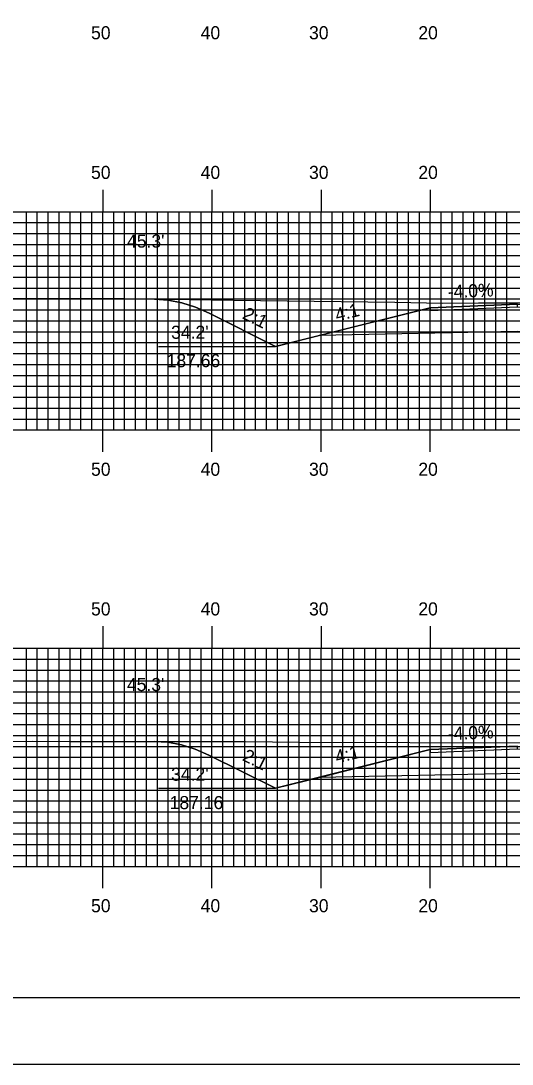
# Model space of a CAD drawing. Extents: x 1798781 to 1799124, y 442591 to 442811.
# Drawn here: x 1798889.5 to 1798934.5, y 442590.5 to 442686.2 of the extents above; entities that cross this region are included whole.
import ezdxf

# ---------------------------------------------------------------- set-up
doc = ezdxf.new("R2010")
doc.units = 0
for name, color, linetype in [('ANNOTATION', 7, 'Continuous'), ('BORDER', 7, 'Continuous'), ('D_Roadway_Centerline', 7, 'Continuous'), ('D_Roadway_Edge_Shoulder', 7, 'Continuous'), ('D_Roadway_SlopeLines', 7, 'Continuous'), ('D_Roadway_SubGrade', 7, 'Continuous'), ('D_Text_Standard', 7, 'Continuous'), ('H_V ANNOTATION', 7, 'Continuous'), ('MAJOR', 7, 'Continuous'), ('MINOR', 7, 'Continuous'), ('PDRAIN', 7, 'Continuous'), ('PLOT BOUNDARY', 7, 'Continuous'), ('S_Roadway_Centerline', 7, 'Continuous')]:
    doc.layers.add(name, color=color, linetype=linetype)

msp = doc.modelspace()

# ---------------------------------------------------------------- linework, layer by layer
at = {"layer": 'BORDER'}
msp.add_lwpolyline([(1798797.384, 442596.665), (1799117.384, 442596.665), (1799117.384, 442806.665), (1798797.384, 442806.665)], close=True, dxfattribs=at)
at = {"layer": 'D_Roadway_Centerline'}
for points in [[(1798901.718, 442660.662), (1798902.968, 442660.566), (1798904.218, 442660.319), (1798905.468, 442659.921), (1798906.718, 442659.371), (1798912.81, 442656.325), (1798916.81, 442657.325), (1798926.984, 442659.869), (1798934.984, 442660.189), (1798946.984, 442659.949), (1798958.984, 442659.709), (1798966.984, 442659.389), (1798977.158, 442656.845), (1798981.158, 442655.845), (1798987.244, 442658.888), (1798988.494, 442659.435), (1798989.744, 442659.826), (1798990.994, 442660.06), (1798992.244, 442660.138)], [(1798901.708, 442620.125), (1798902.958, 442620.047), (1798904.208, 442619.813), (1798905.458, 442619.423), (1798906.708, 442618.876), (1798912.81, 442615.825), (1798916.81, 442616.825), (1798926.984, 442619.369), (1798934.984, 442619.689), (1798946.984, 442619.449), (1798958.984, 442619.209), (1798966.984, 442618.889), (1798977.158, 442616.345), (1798981.158, 442615.345), (1798987.068, 442618.3), (1798988.318, 442618.845), (1798989.568, 442619.228), (1798990.818, 442619.451), (1798992.068, 442619.513)]]:
    msp.add_lwpolyline(points, dxfattribs=at)
at = {"layer": 'D_Roadway_Edge_Shoulder'}
for points in [[(1798934.984, 442660.189), (1798926.984, 442659.869), (1798926.984, 442659.619), (1798934.984, 442659.939)], [(1798934.984, 442619.689), (1798926.984, 442619.369), (1798926.984, 442619.119), (1798934.984, 442619.439)]]:
    msp.add_lwpolyline(points, close=True, dxfattribs=at)
at = {"layer": 'D_Roadway_SlopeLines'}
for points in [[(1798912.81, 442656.325), (1798906.718, 442659.371), (1798905.468, 442659.921), (1798904.218, 442660.319), (1798902.968, 442660.566), (1798901.718, 442660.662)], [(1798926.984, 442659.869), (1798912.81, 442656.325)], [(1798912.81, 442615.825), (1798906.708, 442618.876), (1798905.458, 442619.423), (1798904.208, 442619.813), (1798902.958, 442620.047), (1798901.708, 442620.125)], [(1798926.984, 442619.369), (1798912.81, 442615.825)]]:
    msp.add_lwpolyline(points, dxfattribs=at)
at = {"layer": 'D_Roadway_SubGrade'}
for points in [[(1798934.984, 442657.689), (1798916.81, 442657.325), (1798926.984, 442659.869), (1798926.984, 442659.619), (1798934.984, 442659.939), (1798946.984, 442659.699), (1798958.984, 442659.459), (1798966.984, 442659.139), (1798966.984, 442659.389), (1798977.158, 442656.845), (1798958.984, 442657.209), (1798946.984, 442657.449)], [(1798934.984, 442617.189), (1798916.81, 442616.825), (1798926.984, 442619.369), (1798926.984, 442619.119), (1798934.984, 442619.439), (1798946.984, 442619.199), (1798958.984, 442618.959), (1798966.984, 442618.639), (1798966.984, 442618.889), (1798977.158, 442616.345), (1798958.984, 442616.709), (1798946.984, 442616.949)]]:
    msp.add_lwpolyline(points, close=True, dxfattribs=at)
at = {"layer": 'MAJOR'}
for p, q in [((1798896.984, 442670.669), (1798896.984, 442668.665)), ((1798906.984, 442670.669), (1798906.984, 442668.665)), ((1798916.984, 442670.669), (1798916.984, 442668.665)), ((1798926.984, 442670.669), (1798926.984, 442668.665)), ((1798806.984, 442668.665), (1799086.984, 442668.665)), ((1798806.984, 442668.665), (1799086.984, 442668.665)), ((1798896.984, 442648.665), (1798896.984, 442668.665)), ((1798906.984, 442648.665), (1798906.984, 442668.665)), ((1798916.984, 442648.665), (1798916.984, 442668.665)), ((1798926.984, 442648.665), (1798926.984, 442668.665)), ((1798806.984, 442663.665), (1799086.984, 442663.665)), ((1798806.984, 442658.665), (1799086.984, 442658.665)), ((1798806.984, 442653.665), (1799086.984, 442653.665)), ((1798806.984, 442648.665), (1799086.984, 442648.665)), ((1798806.984, 442648.665), (1799086.984, 442648.665)), ((1798896.984, 442646.661), (1798896.984, 442648.665)), ((1798906.984, 442646.661), (1798906.984, 442648.665)), ((1798916.984, 442646.661), (1798916.984, 442648.665)), ((1798926.984, 442646.661), (1798926.984, 442648.665)), ((1798896.984, 442630.669), (1798896.984, 442628.665)), ((1798906.984, 442630.669), (1798906.984, 442628.665)), ((1798916.984, 442630.669), (1798916.984, 442628.665)), ((1798926.984, 442630.669), (1798926.984, 442628.665)), ((1798806.984, 442628.665), (1799086.984, 442628.665)), ((1798806.984, 442628.665), (1799086.984, 442628.665)), ((1798896.984, 442608.665), (1798896.984, 442628.665)), ((1798906.984, 442608.665), (1798906.984, 442628.665)), ((1798916.984, 442608.665), (1798916.984, 442628.665)), ((1798926.984, 442608.665), (1798926.984, 442628.665)), ((1798806.984, 442623.665), (1799086.984, 442623.665)), ((1798806.984, 442618.665), (1799086.984, 442618.665)), ((1798806.984, 442613.665), (1799086.984, 442613.665)), ((1798806.984, 442608.665), (1799086.984, 442608.665)), ((1798806.984, 442608.665), (1799086.984, 442608.665)), ((1798896.984, 442606.661), (1798896.984, 442608.665)), ((1798906.984, 442606.661), (1798906.984, 442608.665)), ((1798916.984, 442606.661), (1798916.984, 442608.665)), ((1798926.984, 442606.661), (1798926.984, 442608.665))]:
    msp.add_line(p, q, dxfattribs=at)
at = {"layer": 'MINOR'}
for p, q in [((1798889.984, 442648.665), (1798889.984, 442668.665)), ((1798890.984, 442648.665), (1798890.984, 442668.665)), ((1798891.984, 442648.665), (1798891.984, 442668.665)), ((1798892.984, 442648.665), (1798892.984, 442668.665)), ((1798893.984, 442648.665), (1798893.984, 442668.665)), ((1798894.984, 442648.665), (1798894.984, 442668.665)), ((1798895.984, 442648.665), (1798895.984, 442668.665)), ((1798897.984, 442648.665), (1798897.984, 442668.665)), ((1798898.984, 442648.665), (1798898.984, 442668.665)), ((1798899.984, 442648.665), (1798899.984, 442668.665)), ((1798900.984, 442648.665), (1798900.984, 442668.665)), ((1798901.984, 442648.665), (1798901.984, 442668.665)), ((1798902.984, 442648.665), (1798902.984, 442668.665)), ((1798903.984, 442648.665), (1798903.984, 442668.665)), ((1798904.984, 442648.665), (1798904.984, 442668.665)), ((1798905.984, 442648.665), (1798905.984, 442668.665)), ((1798907.984, 442648.665), (1798907.984, 442668.665)), ((1798908.984, 442648.665), (1798908.984, 442668.665)), ((1798909.984, 442648.665), (1798909.984, 442668.665)), ((1798910.984, 442648.665), (1798910.984, 442668.665)), ((1798911.984, 442648.665), (1798911.984, 442668.665)), ((1798912.984, 442648.665), (1798912.984, 442668.665)), ((1798913.984, 442648.665), (1798913.984, 442668.665)), ((1798914.984, 442648.665), (1798914.984, 442668.665)), ((1798915.984, 442648.665), (1798915.984, 442668.665)), ((1798917.984, 442648.665), (1798917.984, 442668.665)), ((1798918.984, 442648.665), (1798918.984, 442668.665)), ((1798919.984, 442648.665), (1798919.984, 442668.665)), ((1798920.984, 442648.665), (1798920.984, 442668.665)), ((1798921.984, 442648.665), (1798921.984, 442668.665)), ((1798922.984, 442648.665), (1798922.984, 442668.665)), ((1798923.984, 442648.665), (1798923.984, 442668.665)), ((1798924.984, 442648.665), (1798924.984, 442668.665)), ((1798925.984, 442648.665), (1798925.984, 442668.665)), ((1798927.984, 442648.665), (1798927.984, 442668.665)), ((1798928.984, 442648.665), (1798928.984, 442668.665)), ((1798929.984, 442648.665), (1798929.984, 442668.665)), ((1798930.984, 442648.665), (1798930.984, 442668.665)), ((1798931.984, 442648.665), (1798931.984, 442668.665)), ((1798932.984, 442648.665), (1798932.984, 442668.665)), ((1798933.984, 442648.665), (1798933.984, 442668.665)), ((1798806.984, 442667.665), (1799086.984, 442667.665)), ((1798806.984, 442666.665), (1799086.984, 442666.665)), ((1798806.984, 442665.665), (1799086.984, 442665.665)), ((1798806.984, 442664.665), (1799086.984, 442664.665)), ((1798806.984, 442662.665), (1799086.984, 442662.665)), ((1798806.984, 442661.665), (1799086.984, 442661.665)), ((1798806.984, 442660.665), (1799086.984, 442660.665)), ((1798806.984, 442659.665), (1799086.984, 442659.665)), ((1798806.984, 442657.665), (1799086.984, 442657.665)), ((1798806.984, 442656.665), (1799086.984, 442656.665)), ((1798806.984, 442655.665), (1799086.984, 442655.665)), ((1798806.984, 442654.665), (1799086.984, 442654.665)), ((1798806.984, 442652.665), (1799086.984, 442652.665)), ((1798806.984, 442651.665), (1799086.984, 442651.665)), ((1798806.984, 442650.665), (1799086.984, 442650.665)), ((1798806.984, 442649.665), (1799086.984, 442649.665)), ((1798889.984, 442608.665), (1798889.984, 442628.665)), ((1798890.984, 442608.665), (1798890.984, 442628.665)), ((1798891.984, 442608.665), (1798891.984, 442628.665)), ((1798892.984, 442608.665), (1798892.984, 442628.665)), ((1798893.984, 442608.665), (1798893.984, 442628.665)), ((1798894.984, 442608.665), (1798894.984, 442628.665)), ((1798895.984, 442608.665), (1798895.984, 442628.665)), ((1798897.984, 442608.665), (1798897.984, 442628.665)), ((1798898.984, 442608.665), (1798898.984, 442628.665)), ((1798899.984, 442608.665), (1798899.984, 442628.665)), ((1798900.984, 442608.665), (1798900.984, 442628.665)), ((1798901.984, 442608.665), (1798901.984, 442628.665)), ((1798902.984, 442608.665), (1798902.984, 442628.665)), ((1798903.984, 442608.665), (1798903.984, 442628.665)), ((1798904.984, 442608.665), (1798904.984, 442628.665)), ((1798905.984, 442608.665), (1798905.984, 442628.665)), ((1798907.984, 442608.665), (1798907.984, 442628.665)), ((1798908.984, 442608.665), (1798908.984, 442628.665)), ((1798909.984, 442608.665), (1798909.984, 442628.665)), ((1798910.984, 442608.665), (1798910.984, 442628.665)), ((1798911.984, 442608.665), (1798911.984, 442628.665)), ((1798912.984, 442608.665), (1798912.984, 442628.665)), ((1798913.984, 442608.665), (1798913.984, 442628.665)), ((1798914.984, 442608.665), (1798914.984, 442628.665)), ((1798915.984, 442608.665), (1798915.984, 442628.665)), ((1798917.984, 442608.665), (1798917.984, 442628.665)), ((1798918.984, 442608.665), (1798918.984, 442628.665)), ((1798919.984, 442608.665), (1798919.984, 442628.665)), ((1798920.984, 442608.665), (1798920.984, 442628.665)), ((1798921.984, 442608.665), (1798921.984, 442628.665)), ((1798922.984, 442608.665), (1798922.984, 442628.665)), ((1798923.984, 442608.665), (1798923.984, 442628.665)), ((1798924.984, 442608.665), (1798924.984, 442628.665)), ((1798925.984, 442608.665), (1798925.984, 442628.665)), ((1798927.984, 442608.665), (1798927.984, 442628.665)), ((1798928.984, 442608.665), (1798928.984, 442628.665)), ((1798929.984, 442608.665), (1798929.984, 442628.665)), ((1798930.984, 442608.665), (1798930.984, 442628.665)), ((1798931.984, 442608.665), (1798931.984, 442628.665)), ((1798932.984, 442608.665), (1798932.984, 442628.665)), ((1798933.984, 442608.665), (1798933.984, 442628.665)), ((1798806.984, 442627.665), (1799086.984, 442627.665)), ((1798806.984, 442626.665), (1799086.984, 442626.665)), ((1798806.984, 442625.665), (1799086.984, 442625.665)), ((1798806.984, 442624.665), (1799086.984, 442624.665)), ((1798806.984, 442622.665), (1799086.984, 442622.665)), ((1798806.984, 442621.665), (1799086.984, 442621.665)), ((1798806.984, 442620.665), (1799086.984, 442620.665)), ((1798806.984, 442619.665), (1799086.984, 442619.665)), ((1798806.984, 442617.665), (1799086.984, 442617.665)), ((1798806.984, 442616.665), (1799086.984, 442616.665)), ((1798806.984, 442615.665), (1799086.984, 442615.665)), ((1798806.984, 442614.665), (1799086.984, 442614.665)), ((1798806.984, 442612.665), (1799086.984, 442612.665)), ((1798806.984, 442611.665), (1799086.984, 442611.665)), ((1798806.984, 442610.665), (1799086.984, 442610.665)), ((1798806.984, 442609.665), (1799086.984, 442609.665))]:
    msp.add_line(p, q, dxfattribs=at)
at = {"layer": 'PDRAIN'}
for p, q in [((1798902.087, 442656.325), (1798912.81, 442656.325)), ((1798902.087, 442615.825), (1798912.81, 442615.825))]:
    msp.add_line(p, q, dxfattribs=at)
at = {"layer": 'PLOT BOUNDARY'}
msp.add_lwpolyline([(1798781.197, 442590.547), (1799121.197, 442590.547), (1799121.197, 442810.547), (1798781.197, 442810.547)], close=True, dxfattribs=at)
at = {"layer": 'S_Roadway_Centerline'}
for points in [[(1798806.984, 442661.39), (1798824.408, 442660.82), (1798828.209, 442660.932), (1798834.625, 442661.029), (1798841.928, 442661.089), (1798858.902, 442660.631), (1798863.81, 442660.668), (1798875.78, 442660.694), (1798887.657, 442660.709), (1798899.002, 442660.707), (1798908.955, 442660.544), (1798923.749, 442660.383), (1798928.119, 442660.286), (1798931.407, 442660.325), (1798938.788, 442660.326), (1798953.832, 442660.479), (1798963.345, 442660.3), (1798972.994, 442660.158), (1798973.928, 442660.149), (1798974.599, 442660.142), (1798997.333, 442660.137), (1798997.392, 442660.137), (1798997.445, 442660.138), (1798998.091, 442660.138)], [(1798806.984, 442620.885), (1798813.86, 442620.917), (1798821.238, 442620.892), (1798833.443, 442620.557), (1798844.008, 442620.447), (1798856.163, 442620.314), (1798865.916, 442620.291), (1798870.321, 442620.255), (1798879.538, 442620.45), (1798887.315, 442620.108), (1798890.507, 442620.154), (1798893.929, 442620.122), (1798910.048, 442620.128), (1798914.998, 442620.056), (1798935.265, 442620.006), (1798942.914, 442619.968), (1798954.485, 442619.943), (1798960.784, 442619.982), (1798967.611, 442619.947), (1798972.456, 442619.973), (1798976.893, 442619.739), (1798992.581, 442619.505), (1798996.493, 442619.544), (1799015.913, 442619.739)]]:
    msp.add_lwpolyline(points, dxfattribs=at)

# ---------------------------------------------------------------- texts
at = {"layer": 'ANNOTATION'}
for s, rotation, p in [('-4.0%', 2.29061, (1798928.616, 442660.736)), ('4:1', 14.03624, (1798918.432, 442658.593)), ('2:1', 333.43495, (1798909.698, 442658.917)), ('-4.0%', 2.29061, (1798928.616, 442620.236)), ('2:1', 333.43495, (1798909.693, 442618.42)), ('4:1', 14.03624, (1798918.432, 442618.093))]:
    msp.add_text(s, height=1.2, rotation=rotation, dxfattribs=at).set_placement(p)
for s, p in [("34.2'", (1798903.248, 442657.017)), ('187.66', (1798902.836, 442654.417)), ("34.2'", (1798903.248, 442616.517)), ('187.16', (1798903.114, 442613.917))]:
    msp.add_text(s, height=1.2, dxfattribs=at).set_placement(p)
at = {"layer": 'D_Text_Standard'}
for p in [(1798899.209, 442665.373), (1798899.198, 442624.733)]:
    msp.add_text("45.3'", height=1.2, dxfattribs=at).set_placement(p)
at = {"layer": 'H_V ANNOTATION'}
for s, p in [('50', (1798895.913, 442684.465)), ('40', (1798905.956, 442684.465)), ('30', (1798915.881, 442684.465)), ('20', (1798925.892, 442684.465)), ('50', (1798895.913, 442671.665)), ('40', (1798905.956, 442671.665)), ('30', (1798915.881, 442671.665)), ('20', (1798925.892, 442671.665)), ('50', (1798895.913, 442644.465)), ('40', (1798905.956, 442644.465)), ('30', (1798915.881, 442644.465)), ('20', (1798925.892, 442644.465)), ('50', (1798895.913, 442631.665)), ('40', (1798905.956, 442631.665)), ('30', (1798915.881, 442631.665)), ('20', (1798925.892, 442631.665)), ('50', (1798895.913, 442604.465)), ('40', (1798905.956, 442604.465)), ('30', (1798915.881, 442604.465)), ('20', (1798925.892, 442604.465))]:
    msp.add_text(s, height=1.2, dxfattribs=at).set_placement(p)

doc.saveas('drawing.dxf')
